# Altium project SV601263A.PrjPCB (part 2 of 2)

## Sheet SV601263A_Power.SchDoc
size 431 x 279 mm; Date: Not shown in title block; ApprovedBy: Not shown in title block; CheckedBy: Not shown in title block; Author: Not shown in title block; CompanyName: Not shown in title block; Engineer: Not shown in title block; Organization: Not shown in title block; Address1: Not shown in title block; Address2: Not shown in title block; Address3: Not shown in title block; Address4: Not shown in title block; DocumentNumber: 9; Revision: Use project parameter SCH_Rev; SheetNumber: 6; SheetTotal: 8; PageSetup: Record=PageOptions¦CenterHorizontal=True¦CenterVertical=True¦PrintScale=0.96¦XCorrection=1.00¦YCorrection=1.00¦PrintKind=0¦BorderSize=5000000¦LeftOffset=0¦BottomOffset=0¦Orientation=2¦PaperLength=1000¦PaperWidth=1000¦Scale=100¦PaperSource=15¦PrintQuality=600¦MediaType=1¦DitherType=10¦PaperKind=11x17¦PrintScaleMode=1
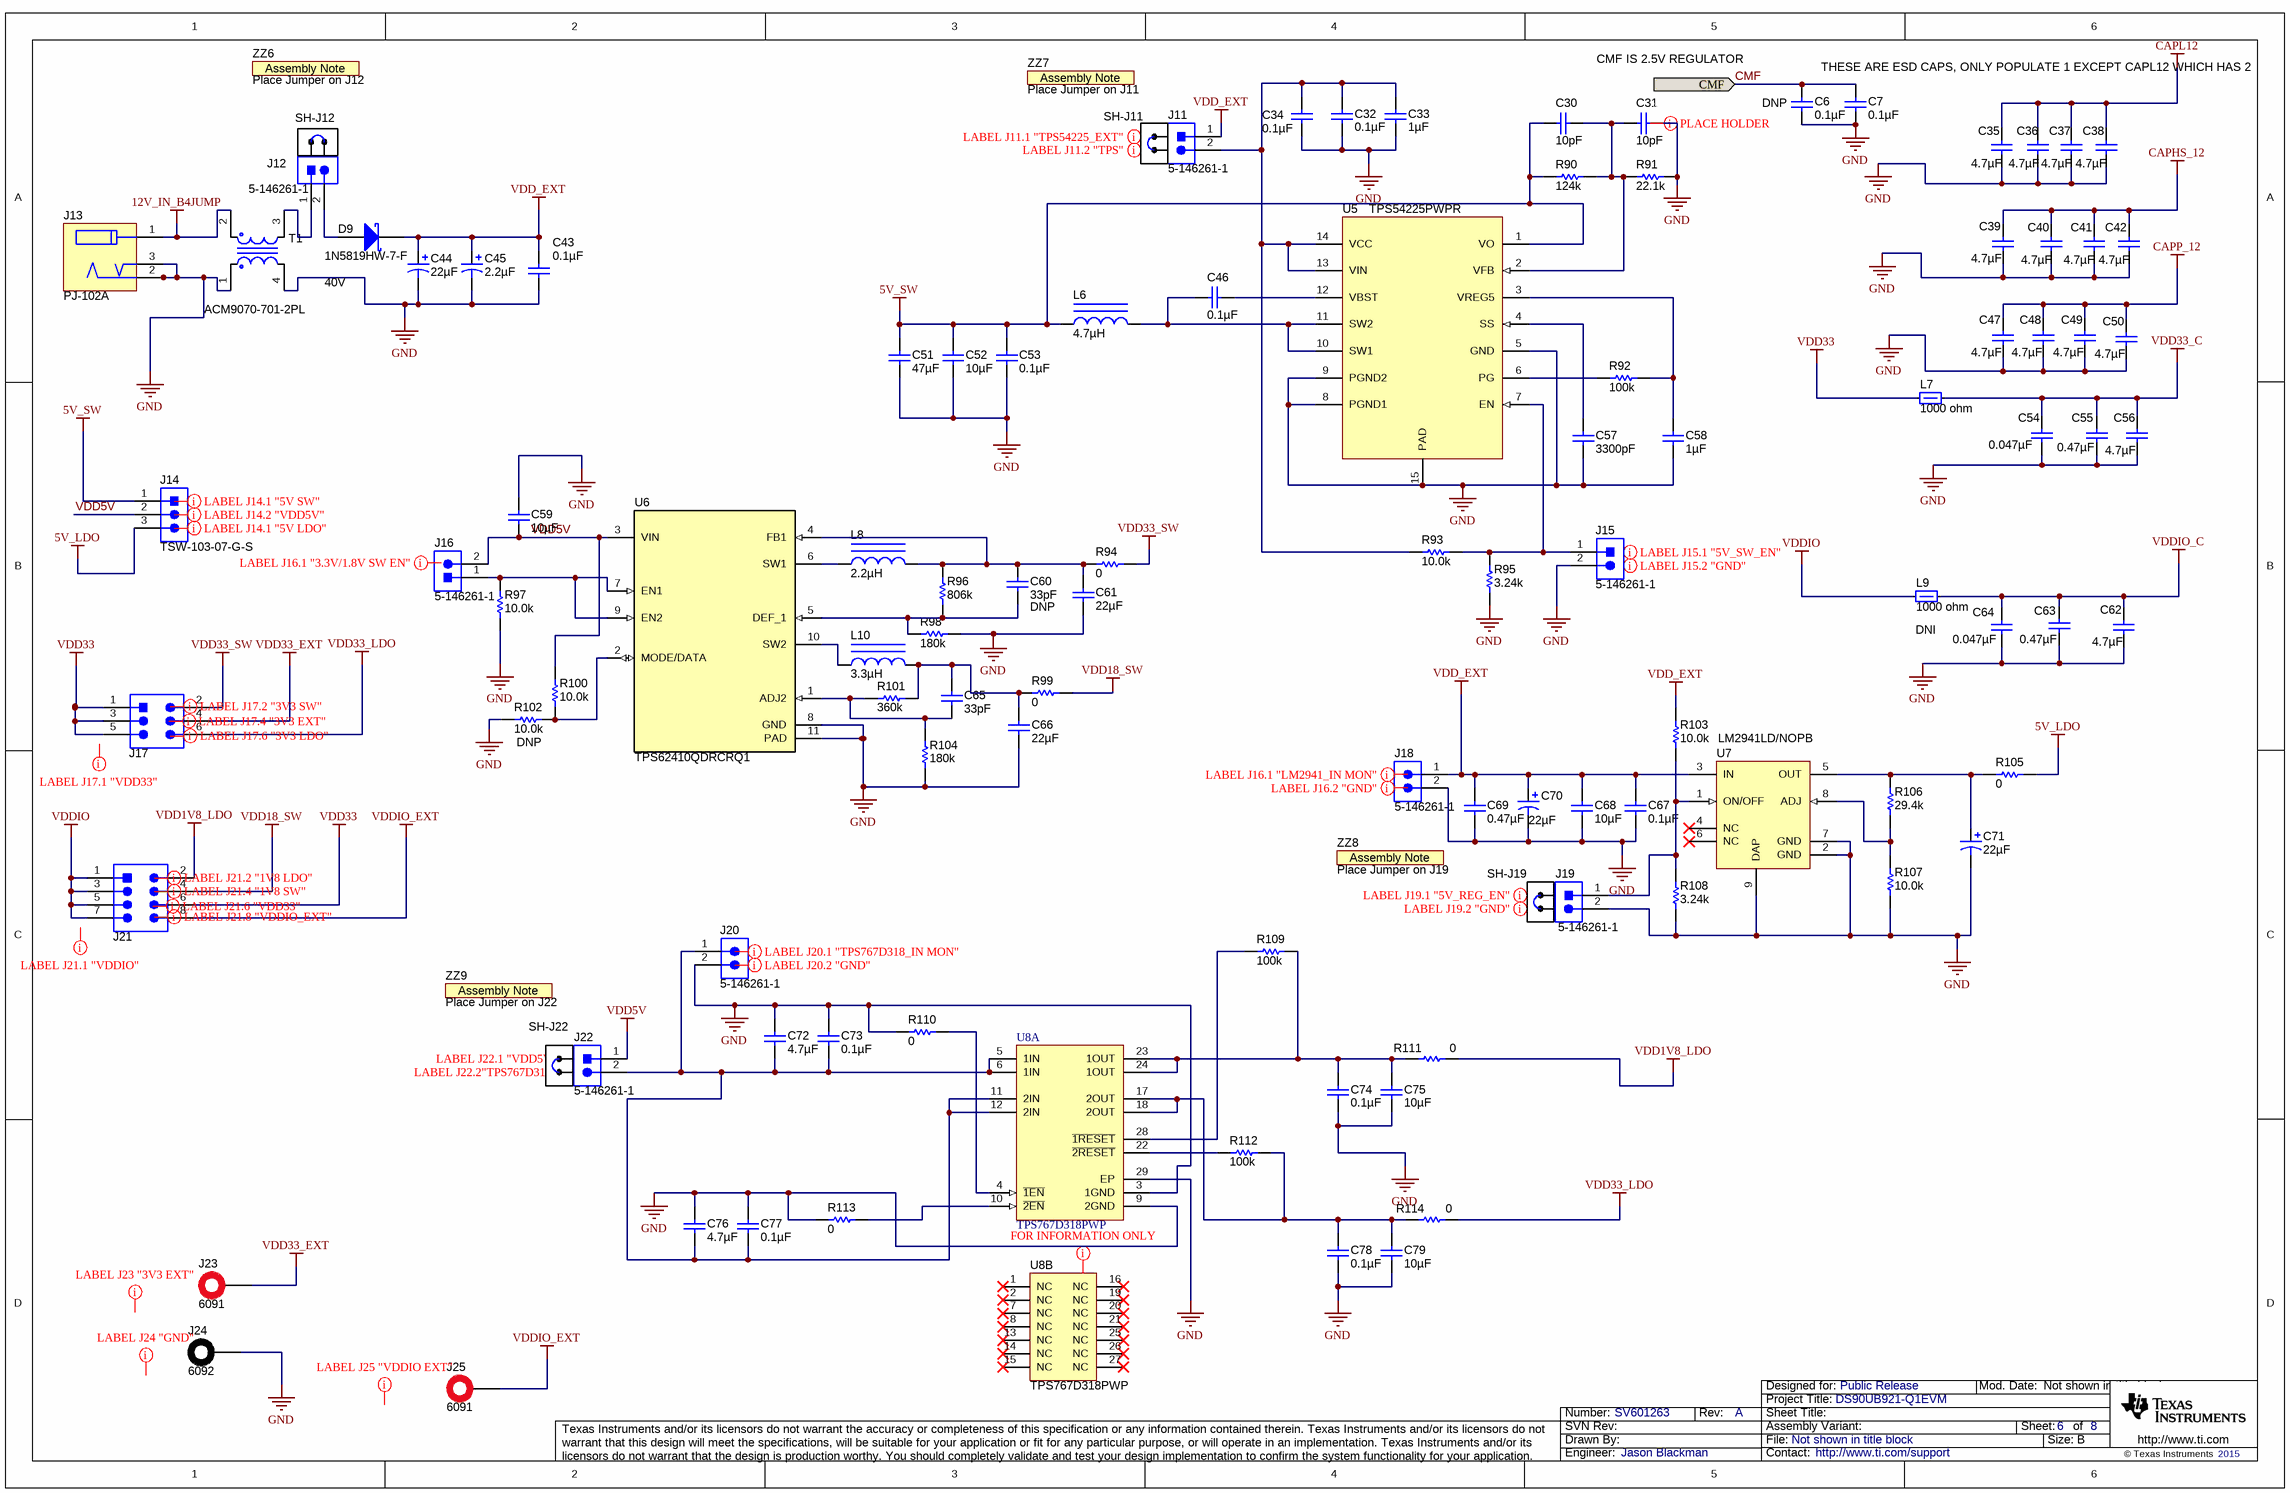
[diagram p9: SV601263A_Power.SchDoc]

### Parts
C6  DNP  ValueDisplayed: 0.1µF  [0603]
C7  ValueDisplayed: 0.1µF  [0603]  (hidden comment: GRM188R61C104KA01D)
C30  ValueDisplayed: 10pF  [0402]  (hidden comment: GRM1555C1H100JA01D)
C31  ValueDisplayed: 10pF  [0402]  (hidden comment: GRM1555C1H100JA01D)
C32  ValueDisplayed: 0.1µF  [0402]  (hidden comment: GRM155R71C104KA88D)
C33  ValueDisplayed: 1µF  [0603]  (hidden comment: C1608X7R1C105K080AC)
C34  ValueDisplayed: 0.1µF  [0402]  (hidden comment: GRM155R71C104KA88D)
C35  ValueDisplayed: 4.7µF  [0805_HV]  (hidden comment: GCM21BR71C475KA73L)
C36  ValueDisplayed: 4.7µF  [0805_HV]  (hidden comment: GCM21BR71C475KA73L)
C37  ValueDisplayed: 4.7µF  [0805_HV]  (hidden comment: GCM21BR71C475KA73L)
C38  ValueDisplayed: 4.7µF  [0805_HV]  (hidden comment: GCM21BR71C475KA73L)
C39  ValueDisplayed: 4.7µF  [0805_HV]  (hidden comment: GCM21BR71C475KA73L)
C40  ValueDisplayed: 4.7µF  [0805_HV]  (hidden comment: GCM21BR71C475KA73L)
C41  ValueDisplayed: 4.7µF  [0805_HV]  (hidden comment: GCM21BR71C475KA73L)
C42  ValueDisplayed: 4.7µF  [0805_HV]  (hidden comment: GCM21BR71C475KA73L)
C43  ValueDisplayed: 0.1µF  [0402]  (hidden comment: GRM155R71C104KA88D)
C44  ValueDisplayed: 22µF  [7343-31]  (hidden comment: 293D226X0025D2TE3)
C45  ValueDisplayed: 2.2µF  [3216-18]  (hidden comment: 293D225X9025A2TE3)
C46  ValueDisplayed: 0.1µF  [0402]  (hidden comment: GRM155R71C104KA88D)
C47  ValueDisplayed: 4.7µF  [0805_HV]  (hidden comment: GCM21BR71C475KA73L)
C48  ValueDisplayed: 4.7µF  [0805_HV]  (hidden comment: GCM21BR71C475KA73L)
C49  ValueDisplayed: 4.7µF  [0805_HV]  (hidden comment: GCM21BR71C475KA73L)
C50  ValueDisplayed: 4.7µF  [0805_HV]  (hidden comment: GCM21BR71C475KA73L)
C51  ValueDisplayed: 47µF  [1210]  (hidden comment: GRM32ER61C476ME15L)
C52  ValueDisplayed: 10µF  [0805_HV]  (hidden comment: GRM21BR71A106KE51L)
C53  ValueDisplayed: 0.1µF  [0402]  (hidden comment: GRM155R71C104KA88D)
C54  ValueDisplayed: 0.047µF  [0402]  (hidden comment: GRM155R71C473KA01D)
C55  ValueDisplayed: 0.47µF  [0603]  (hidden comment: GRM188R71E474KA12D)
C56  ValueDisplayed: 4.7µF  [0805_HV]  (hidden comment: GCM21BR71C475KA73L)
C57  ValueDisplayed: 3300pF  [0402]  (hidden comment: GRM155R71H332KA01D)
C58  ValueDisplayed: 1µF  [0603]  (hidden comment: C1608X7R1C105K080AC)
C59  ValueDisplayed: 10µF  [0603]  (hidden comment: GRM188R61E106MA73D)
C60  DNP  ValueDisplayed: 33pF  [0603]
C61  ValueDisplayed: 22µF  [1206_190]  (hidden comment: C3216X5R1V226M160AC)
C62  ValueDisplayed: 4.7µF  [0805_HV]  (hidden comment: GCM21BR71C475KA73L)
C63  ValueDisplayed: 0.47µF  [0603]  (hidden comment: GRM188R71E474KA12D)
C64  ValueDisplayed: 0.047µF  [0402]  (hidden comment: GRM155R71C473KA01D)
C65  ValueDisplayed: 33pF  [0603]  (hidden comment: 06035A330JAT2A)
C66  ValueDisplayed: 22µF  [1206_190]  (hidden comment: C3216X5R1V226M160AC)
C67  ValueDisplayed: 0.1µF  [0402]  (hidden comment: C1005X7R1H104K050BB)
C68  ValueDisplayed: 10µF  [0603]  (hidden comment: GRM188R61E106MA73D)
C69  ValueDisplayed: 0.47µF  [0402]  (hidden comment: GRM155R61C474KE01)
C70  ValueDisplayed: 22µF  [7343-31]  (hidden comment: 293D226X0025D2TE3)
C71  ValueDisplayed: 22µF  [7343-31]  (hidden comment: 293D226X0025D2TE3)
C72  ValueDisplayed: 4.7µF  [0805_HV]  (hidden comment: GRM21BR71C475KA73L)
C73  ValueDisplayed: 0.1µF  [0402]  (hidden comment: GRM155R71C104KA88D)
C74  ValueDisplayed: 0.1µF  [0402]  (hidden comment: GRM155R71C104KA88D)
C75  ValueDisplayed: 10µF  [0805_HV]  (hidden comment: GRM21BR71A106KE51L)
C76  ValueDisplayed: 4.7µF  [0805_HV]  (hidden comment: GRM21BR71C475KA73L)
C77  ValueDisplayed: 0.1µF  [0402]  (hidden comment: GRM155R71C104KA88D)
C78  ValueDisplayed: 0.1µF  [0402]  (hidden comment: GRM155R71C104KA88D)
C79  ValueDisplayed: 10µF  [0805_HV]  (hidden comment: GRM21BR71A106KE51L)
D9  1N5819HW-7-F  value 40V  [SOD-123]
J11  5-146261-1  [CONN_5-146261-1]
J12  5-146261-1  [CONN_5-146261-1]
J13  PJ-102A  [CONN_PJ-102A]
J14  TSW-103-07-G-S  [TSW-103-07-G-S]
J15  5-146261-1  [CONN_5-146261-1]
J16  5-146261-1  [CONN_5-146261-1]
J17  TSW-103-07-G-D  [TSW-103-07-G-D]  (value not drawn)
J18  5-146261-1  [CONN_5-146261-1]
J19  5-146261-1  [CONN_5-146261-1]
J20  5-146261-1  [CONN_5-146261-1]
J21  TSW-104-07-G-D  [TSW-104-07-G-D]  (value not drawn)
J22  5-146261-1  [CONN_5-146261-1]
J23  6091  [6091]
J24  6092  [6092]
J25  6091  [6091]
L6  ValueDisplayed: 4.7µH  [WE-TPC-XLH2]  (hidden comment: 7440650047)
L7  value 1000 ohm  [0402]  (hidden comment: BLM15AX102SN1D)
L8  ValueDisplayed: 2.2µH  [VLF302510MT]  (hidden comment: VLF302510MT-2R2M)
L9  value 1000 ohm  [0402]  (hidden comment: BLM15AX102SN1D)
L10  ValueDisplayed: 3.3µH  [MLP2520S-S]  (hidden comment: MLP2520S3R3ST0S1)
R90  value 124k  [0402]  (hidden comment: CRCW0402124KFKED)
R91  value 22.1k  [0402]  (hidden comment: CRCW040222K1FKED)
R92  value 100k  [0402]  (hidden comment: CRCW0402100KJNED)
R93  ValueDisplayed: 10.0k  [0402]  (hidden comment: CRCW040210K0FKED)
R94  value 0  [0402]  (hidden comment: ERJ-2GE0R00X)
R95  value 3.24k  [0402]  (hidden comment: CRCW04023K24FKED)
R96  ValueDisplayed: 806k  [0805_HV]  (hidden comment: RT0805BRD07806KL)
R97  ValueDisplayed: 10.0k  [0402]  (hidden comment: CRCW040210K0FKED)
R98  ValueDisplayed: 180k  [0603]  (hidden comment: RG1608P-184-B-T5)
R99  value 0  [0402]  (hidden comment: ERJ-2GE0R00X)
R100  ValueDisplayed: 10.0k  [0402]  (hidden comment: CRCW040210K0FKED)
R101  ValueDisplayed: 360k  [0603]  (hidden comment: ERJ-3EKF3603V)
R102  DNP  ValueDisplayed: 10.0k  [0402]
R103  ValueDisplayed: 10.0k  [0402]  (hidden comment: CRCW040210K0FKED)
R104  ValueDisplayed: 180k  [0603]  (hidden comment: RG1608P-184-B-T5)
R105  value 0  [0402]  (hidden comment: ERJ-2GE0R00X)
R106  ValueDisplayed: 29.4k  [0402]  (hidden comment: CRCW040229K4FKED)
R107  ValueDisplayed: 10.0k  [0402]  (hidden comment: CRCW040210K0FKED)
R108  value 3.24k  [0402]  (hidden comment: CRCW04023K24FKED)
R109  value 100k  [0402]  (hidden comment: CRCW0402100KJNED)
R110  value 0  [0402]  (hidden comment: ERJ-2GE0R00X)
R111  ValueDisplayed: 0  [0603]  (hidden comment: CRCW06030000Z0EA)
R112  value 100k  [0402]  (hidden comment: CRCW0402100KJNED)
R113  value 0  [0402]  (hidden comment: ERJ-2GE0R00X)
R114  ValueDisplayed: 0  [0603]  (hidden comment: CRCW06030000Z0EA)
SH-J11  969102-0000-DA  [SNT-100-BK-G]  (value not drawn)
SH-J12  969102-0000-DA  [SNT-100-BK-G]  (value not drawn)
SH-J19  969102-0000-DA  [SNT-100-BK-G]  (value not drawn)
SH-J22  969102-0000-DA  [SNT-100-BK-G]  (value not drawn)
T1  ACM9070-701-2PL  [ACM9070]
U5  TPS54225PWPR  [PWP0014E_N]
U6  TPS62410QDRCRQ1  [DRC0010J]
U7  LM2941LD/NOPB  [LDC08A]
U8  TPS767D318PWP  [PWP0028D_N]  (parts A,B of 2)
ZZ6  Place Jumper on J12  [AssemblyNote]  (no BOM)
ZZ7  Place Jumper on J11  [AssemblyNote]  (no BOM)
ZZ8  Place Jumper on J19  [AssemblyNote]  (no BOM)
ZZ9  Place Jumper on J22  [AssemblyNote]  (no BOM)

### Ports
CMF

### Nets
5V_LDO: J14.3 R105.2
5V_SW: C30.2 C51.1 C52.1 C53.2 J14.1 L6.1 R90.1 U5.1(VO)
12V_IN_B4JUMP: J13.1 T1.2
CAPHS_12: C39.1 C40.1 C41.1 C42.1
CAPL12: C35.1 C36.1 C37.1 C38.1
CAPP_12: C47.1 C48.1 C49.1 C50.1
GND: C6.2 C7.2 C31.1 C32.2 C33.2 C34.2 C35.2 C36.2 C37.2 C38.2 C39.2 C40.2 C41.2 C42.2 C43.1 C44.2(-) C45.2(-) C47.2 C48.2 C49.2 C50.2 C51.2 C52.2 C53.1 C54.2 C55.2 C56.2 C57.2 C58.2 C59.1 C61.2 C62.2 C63.2 C64.2 C66.2 C67.2 C68.2 C69.2 C70.2(-) C71.2(-) C72.1 C73.2 C74.1 C75.2 C76.1 C77.2 C78.1 C79.2 J13.2 J13.3 J15.2 J18.2 J19.2 J20.2 J24.1 R91.2 R95.1 R97.1 R98.1 R102.1 R104.1 R107.1 R108.1 R110.1 R113.1 T1.1 T1.4 U5.5(GND) U5.8(PGND1) U5.9(PGND2) U5.15(PAD) U6.8(GND) U6.11(PAD) U7.2(GND) U7.7(GND) U7.9(DAP) U8.3(1GND) U8.9(2GND) U8.29(EP)
VDD1V8_LDO: J21.2 R111.2
VDD5V: C59.2 J14.2 J16.2 J22.1 R100.2 U6.3(VIN)
VDD18_SW: J21.4 R99.2
VDD33: J17.1 J17.3 J17.5 J21.6 L7.1
VDD33_C: C54.1 C55.1 C56.1 L7.2
VDD33_EXT: J17.4 J23.1
VDD33_LDO: J17.6 R114.2
VDD33_SW: J17.2 R94.2
VDD_EXT: C43.2 C44.1(+) C45.1(+) C67.1 C68.1 C69.1 C70.1(+) D9.1(K) J11.1 J18.1 R103.2 U7.3(IN)
VDDIO: J21.1 J21.3 J21.5 J21.7 L9.1
VDDIO_C: C62.1 C63.1 C64.1 L9.2
VDDIO_EXT: J21.8 J25.1
CMF: C6.1 C7.1 ; port CMF
NetC30_1: C30.1 C31.2 R90.2 R91.1 U5.2(VFB)
NetC32_1: C32.1 C33.1 C34.1 J11.2 R93.1 U5.13(VIN) U5.14(VCC)
NetC46_1: C46.1 U5.12(VBST)
NetC46_2: C46.2 L6.2 U5.10(SW1) U5.11(SW2)
NetC57_1: C57.1 U5.4(SS)
NetC58_1: C58.1 R92.2 U5.3(VREG5)
NetC60_1: C60.1 C61.1 L8.2 R94.1 R96.1 U6.4(FB1)
NetC60_2: C60.2 R96.2 R98.2 U6.5(DEF_1)
NetC65_1: C65.1 C66.1 L10.2 R99.1 R101.2
NetC65_2: C65.2 R101.1 R104.2 U6.1(ADJ2)
NetC71_1: C71.1(+) R105.1 R106.2 U7.5(OUT)
NetC72_2: C72.2 C73.1 C76.2 C77.1 J20.1 J22.2 U8.5(1IN) U8.6(1IN) U8.11(2IN) U8.12(2IN)
NetC74_2: C74.2 C75.1 R109.1 R111.1 U8.23(1OUT) U8.24(1OUT)
NetC78_2: C78.2 C79.1 R112.2 R114.1 U8.17(2OUT) U8.18(2OUT)
NetD9_2: D9.2(A) J12.2
NetJ12_1: J12.1 T1.3
NetJ15_1: J15.1 R93.2 R95.2 U5.7(EN)
NetJ16_1: J16.1 R97.2 U6.7(EN1) U6.9(EN2)
NetJ19_1: J19.1 R103.1 R108.2 U7.1(ON/OFF)
NetL8_1: L8.1 U6.6(SW1)
NetL10_1: L10.1 U6.10(SW2)
NetR92_1: R92.1 U5.6(PG)
NetR100_1: R100.1 R102.2 U6.2(MODE/DATA)
NetR106_1: R106.1 R107.2 U7.8(ADJ)
NetR109_2: R109.2 U8.28(~{1RESET})
NetR110_2: R110.2 U8.4(~{1EN})
NetR112_1: R112.1 U8.22(~{2RESET})
NetR113_2: R113.2 U8.10(~{2EN})

Not connected (* = marked no-connect by the designer): U7 4(NC)* 6(NC)*; U8 1(NC)* 2(NC)* 7(NC)* 8(NC)* 13(NC)* 14(NC)* 15(NC)* 16(NC)* 19(NC)* 20(NC)* 21(NC)* 25(NC)* 26(NC)* 27(NC)*

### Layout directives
rule Undefined: (no net found under the mark)

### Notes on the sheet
- CMF IS 2.5V REGULATOR
- (near C7) THESE ARE ESD CAPS, ONLY POPULATE 1 EXCEPT CAPL12 WHICH HAS 2
- (near L9) DNI

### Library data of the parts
C6 C7 = GRM188R61C104KA01D: CAP, CERM, 0.1 µF, 16 V, +/- 10%, X5R, 0603; Manufacturer: MuRata; Polarized: N; CompType: Capacitor; Value: 0.1uF; U/M: EA; Cap_F: 0.0000001; Tolerance_%: 10; Value1: Unknown; VDC_V: 16; Value2: 16V; TaMin_C: -55; TaMax_C: 85; AEC Category: Q200
C30 C31 = GRM1555C1H100JA01D: CAP, CERM, 10pF, 50V, +/-5%, C0G/NP0, 0402; Manufacturer: MuRata; Polarized: N; CompType: Capacitor; U/M: EA; Cap_F: 0.00000000001; Tolerance_%: 5; Value1: Unknown; VDC_V: 50; TaMin_C: -55; TaMax_C: 125
C32 C34 C43 C46 C53 C73 C74 C77 C78 = GRM155R71C104KA88D: CAP, CERM, 0.1uF, 16V, +/-10%, X7R, 0402; Manufacturer: MuRata; Polarized: N; CompType: Capacitor; U/M: EA; Cap_F: 0.0000001; Tolerance_%: 10; Value1: Unknown; VDC_V: 16; TaMin_C: -55; TaMax_C: 125
C33 C58 = C1608X7R1C105K080AC: CAP, CERM, 1 µF, 16 V, +/- 10%, X7R, 0603; Manufacturer: TDK; Polarized: N; CompType: Capacitor; Value: 1uF; U/M: EA; Cap_F: 0.000001; Tolerance_%: 10; ESR_ohm: 0.0057; Value1: 0.0057 ohm; VDC_V: 16; Value2: 16V; TaMin_C: -55; TaMax_C: 125; AEC Category: Q200
C35-C42 C47-C50 C56 C62 = GCM21BR71C475KA73L: CAP, CERM, 4.7 µF, 16 V, +/- 10%, X7R, AEC-Q200 Grade 1, 0805; Manufacturer: MuRata; Polarized: N; CompType: Capacitor; Value: 4.7uF; U/M: EA; Cap_F: 0.0000047; Tolerance_%: 10; Value1: Unknown; VDC_V: 16; Value2: 16V; TaMin_C: -55; TaMax_C: 125; Cap_Case: 0805; AEC Category: Q200; AEC Qualified: Y; AEC Grade: 1
C44 C70 C71 = 293D226X0025D2TE3: CAP, TA, 22uF, 25V, +/-20%, 0.7 ohm, SMD; Manufacturer: Vishay-Sprague; Polarized: Y; CompType: Capacitor; U/M: EA; Cap_F: 0.000022; Tolerance_%: 20; Value1: 0.7 ohm; VDC_V: 25; ESR_Ohm: 0.7; IRMS_A: 0.46; TaMin_C: -55; TaMax_C: 125; Cap_Case: D
C45 = 293D225X9025A2TE3: CAP, TA, 2.2uF, 25V, +/-10%, 6.3 ohm, SMD; Manufacturer: Vishay-Sprague; Polarized: Y; CompType: Capacitor; U/M: EA; Cap_F: 0.0000022; Tolerance_%: 10; Value1: 6.3 ohm; VDC_V: 25; ESR_Ohm: 6.3; IRMS_A: 0.11; TaMin_C: -55; TaMax_C: 125; Cap_Case: A
C51 = GRM32ER61C476ME15L: CAP, CERM, 47uF, 16V, +/-20%, X5R, 1210; Manufacturer: MuRata; Polarized: N; CompType: Capacitor; U/M: EA; Cap_F: 0.000047; Tolerance_%: 20; ESR_Ohm: 0.002; Value1: 0.002 ohm; VDC_V: 16; TaMin_C: -55; TaMax_C: 85
C52 C75 C79 = GRM21BR71A106KE51L: CAP, CERM, 10uF, 10V, +/-10%, X7R, 0805; Manufacturer: MuRata; Polarized: N; CompType: Capacitor; U/M: EA; Cap_F: 0.00001; Tolerance_%: 10; ESR_Ohm: 0.003; Value1: 0.003 ohm; TaMin_C: -55; TaMax_C: 125; Cap_Case: 0805
C54 C64 = GRM155R71C473KA01D: CAP, CERM, 0.047 µF, 16 V, +/- 10%, X7R, 0402; Manufacturer: MuRata; Polarized: N; CompType: Capacitor; Value: 0.047uF; U/M: EA; Cap_F: 0.000000047; Tolerance_%: 10; Value1: Unknown; VDC_V: 16; Value2: 16V; TaMin_C: -55; TaMax_C: 125; AEC Category: Q200
C55 C63 = GRM188R71E474KA12D: CAP, CERM, 0.47 µF, 25 V, +/- 10%, X7R, 0603; Manufacturer: MuRata; Polarized: N; CompType: Capacitor; Value: 0.47uF; U/M: EA; Cap_F: 0.00000047; Tolerance_%: 10; Value1: Unknown; VDC_V: 25; Value2: 25V; TaMin_C: -55; TaMax_C: 125; AEC Category: Q200
C57 = GRM155R71H332KA01D: CAP, CERM, 3300pF, 50V, +/-10%, X7R, 0402; Manufacturer: MuRata; Polarized: N; CompType: Capacitor; U/M: EA; Cap_F: 0.0000000033; Tolerance_%: 10; Value1: Unknown; VDC_V: 50; TaMin_C: -55; TaMax_C: 125
C59 C68 = GRM188R61E106MA73D: CAP, CERM, 10 µF, 25 V, +/- 20%, X5R, 0603; Manufacturer: MuRata; Polarized: N; CompType: Capacitor; Value: 10uF; U/M: EA; Cap_F: 0.00001; Tolerance_%: 20; Value1: Unknown; VDC_V: 25; Value2: 25V; TaMin_C: -55; TaMax_C: 85; AEC Category: Q200
C60 C65 = 06035A330JAT2A: CAP, CERM, 33 pF, 50 V, +/- 5%, C0G/NP0, 0603; Manufacturer: AVX; Polarized: N; CompType: Capacitor; Value: 33pF; U/M: EA; Cap_F: 0.000000000033; Tolerance_%: 5; ESR_ohm: 0.209; Value1: 0.209 ohm; VDC_V: 50; Value2: 50V; TaMin_C: -55; TaMax_C: 125; AEC Category: Q200
C61 C66 = C3216X5R1V226M160AC: CAP, CERM, 22 µF, 35 V, +/- 20%, X5R, 1206_190; Manufacturer: TDK; Polarized: N; CompType: Capacitor; Value: 22uF; U/M: EA; Cap_F: 0.000022; Tolerance_%: 20; ESR_ohm: 0.002246; Value1: 0.002246 ohm; VDC_V: 35; Value2: 35V; TaMin_C: -55; TaMax_C: 85; Cap_Case: 1206; AEC Category: Q200
C67 = C1005X7R1H104K050BB: CAP, CERM, 0.1 µF, 50 V, +/- 10%, X7R, 0402; Manufacturer: TDK; Polarized: N; CompType: Capacitor; Value: 0.1uF; U/M: EA; Cap_F: 0.0000001; Tolerance_%: 10; Value1: Unknown; VDC_V: 50; Value2: 50V; TaMin_C: -55; TaMax_C: 125; AEC Category: Q200
C69 = GRM155R61C474KE01: CAP, CERM, 0.47 µF, 16 V, +/- 10%, X5R, 0402; Manufacturer: MuRata; Polarized: N; CompType: Capacitor; Value: 0.47uF; U/M: EA; Cap_F: 0.00000047; Tolerance_%: 10; Value1: Unknown; VDC_V: 16; Value2: 16V; TaMin_C: -55; TaMax_C: 85; AEC Category: Q200
C72 C76 = GRM21BR71C475KA73L: CAP, CERM, 4.7uF, 16V, +/-10%, X7R, 0805; Manufacturer: MuRata; Polarized: N; CompType: Capacitor; U/M: EA; Cap_F: 0.0000047; Tolerance_%: 10; ESR_Ohm: 0.006; Value1: 0.006 ohm; VDC_V: 16; TaMin_C: -55; TaMax_C: 125; Cap_Case: 0805
D9 = 1N5819HW-7-F: Diode, Schottky, 40V, 1A, SOD-123; Manufacturer: Diodes Inc.; U/M: EA; Vf_V: 0.45; Value2: 0.45V; Io_A: 1; Vr_V: 40; TJmax_C: 125
J11 J12 J15 J16 J18-J20 J22 = 5-146261-1: Header, 100mil, 2x1, Gold, TH; Manufacturer: TE Connectivity; SymbolCreator: a0412235; U/M: EA
J13 = PJ-102A: Connector, DC Jack 2.1X5.5 mm, TH; Manufacturer: CUI Inc.; SymbolCreator: a0799628; U/M: EA
J14 = TSW-103-07-G-S: Header, 100mil, 3x1, Gold, TH; Manufacturer: Samtec; SymbolCreator: a0799628; U/M: EA
J17 = TSW-103-07-G-D: Header, 100mil, 3x2, Gold, TH; Manufacturer: Samtec; SymbolCreator: a0412235; Pitch_mm: 2.54; Gender: Male; Shrouded: N; Row_Count: 2; Current_A: 6.3; Voltage_V: 550; Cert_CSA: Y
J21 = TSW-104-07-G-D: Header, 100mil, 4x2, Gold, TH; Manufacturer: Samtec; SymbolCreator: a0411947; Pitch_mm: 2.54; Gender: Male; Shrouded: N; Row_Count: 2; Current_A: 6.3; Voltage_V: 550; Cert_CSA: Y
J23 J25 = 6091: Standard Banana Jack, Insulated, Red; Manufacturer: Keystone; SymbolCreator: a0412235; CompType: Connector; U/M: EA
J24 = 6092: Standard Banana Jack, Insulated, Black; Manufacturer: Keystone; SymbolCreator: a0412235; CompType: Connector; U/M: EA
L6 = 7440650047: Inductor, Shielded Drum Core, Ferrite, 4.7 µH, 4.2 A, 0.02 ohm, SMD; Manufacturer: Wurth Elektronik; Value: 4.7uH; Ind_H: 4.7E-6; Imax_A: 4.2; Irms: 4.6A @ 30C rise; Isat: 4.2A @ 35% inductance drop; DCR_ohm: 0.02; Value2: 4.2A; AEC Category: Q200
L7 L9 = BLM15AX102SN1D: Ferrite Bead, 1000 ohm @ 100 MHz, 0.35 A, 0402; Manufacturer: MuRata; Imax_A: 0.35; DCR_ohm: 0.49; Value1: 0.49 ohm; Value2: 0.35A; ZTyp@100MHz_Ohm: 1000
L8 = VLF302510MT-2R2M: Inductor, Shielded, Ferrite, 2.2 µH, 1.23 A, 0.084 ohm, SMD; Manufacturer: TDK; Value: 2.2uH; Ind_H: 2.2E-6; Imax_A: 1.23; Irms: 1.5A @ 40C rise; Isat: 1.23A @ 30% inductance drop; DCR_ohm: 0.084; Value2: 1.23A; AEC Category: Q200
L10 = MLP2520S3R3ST0S1: Inductor, Multilayer, Ferrite, 3.3 µH, 0.6 A, 0.143 ohm, SMD; Manufacturer: TDK; Value: 3.3uH; Ind_H: 3.3E-6; Imax_A: 0.6; Irms: 1.4A @ 40C rise; Isat: 0.6A @ 30% inductance drop; DCR_ohm: 0.143; Value2: 0.6A; AEC Category: Q200
R90 = CRCW0402124KFKED: RES, 124k ohm, 1%, 0.063W, 0402; Manufacturer: Vishay-Dale; CompType: Resistor; Res_ohm: 124000; Tolerance_%: 1; Power_W: 0.063; VDC_V: 50; TempCo: 100 ppm/C; EIA_Code: E96; U/M: EA
R91 = CRCW040222K1FKED: RES, 22.1k ohm, 1%, 0.063W, 0402; Manufacturer: Vishay-Dale; CompType: Resistor; Res_ohm: 22100; Value_Code: 22k1; Tolerance_%: 1; Power_W: 0.063; VDC_V: 50; TempCo: 100 ppm/C; EIA_Code: E96; U/M: EA
R92 R109 R112 = CRCW0402100KJNED: RES, 100k ohm, 5%, 0.063W, 0402; Manufacturer: Vishay-Dale; CompType: Resistor; Res_ohm: 100000; Tolerance_%: 5; Power_W: 0.063; VDC_V: 50; TempCo: 200 ppm/C; EIA_Code: E24; U/M: EA
R93 R97 R100 R102 R103 R107 = CRCW040210K0FKED: RES, 10.0 k, 1%, 0.063 W, 0402; Manufacturer: Vishay-Dale; CompType: Resistor; Value: 10.0k; Res_ohm: 10000; Value_Code: 10k0; Tolerance_%: 1; Power_W: 0.063; Value2: 0.063W; VDC_V: 50; TempCo: 100 ppm/C; EIA_Code: E96; U/M: EA
R94 R99 R105 R110 R113 = ERJ-2GE0R00X: RES, 0 ohm, 5%, 0.063W, 0402; Manufacturer: Panasonic; CompType: Resistor; Value_Code: 0000; Tolerance_%: 5; Power_W: 0.063; VDC_V: 50; TempCo: 600 ppm/C; EIA_Code: E24; U/M: EA
R95 R108 = CRCW04023K24FKED: RES, 3.24k ohm, 1%, 0.063W, 0402; Manufacturer: Vishay-Dale; CompType: Resistor; Res_ohm: 3240; Value_Code: 3k24; Tolerance_%: 1; Power_W: 0.063; VDC_V: 50; TempCo: 100 ppm/C; EIA_Code: E96; U/M: EA
R96 = RT0805BRD07806KL: RES, 806 k, 0.1%, 0.125 W, 0805; Manufacturer: Yageo America; CompType: Resistor; Value: 806k; Res_ohm: 806000; Tolerance_%: 0.1; Power_W: 0.125; Value2: 0.125W; VDC_V: 150; TempCo: 25 ppm/C; EIA_Code: E192; U/M: EA; AEC Category: Q200
R98 R104 = RG1608P-184-B-T5: RES, 180 k, 0.1%, 0.1 W, 0603; Manufacturer: Susumu Co Ltd; CompType: Resistor; Value: 180k; Res_ohm: 180000; Tolerance_%: 0.1; Value2: 0.1W; VDC_V: 75; TempCo: 25 ppm/C; EIA_Code: E192; U/M: EA; AEC Category: Q200
R101 = ERJ-3EKF3603V: RES, 360 k, 1%, 0.1 W, AEC-Q200 Grade 0, 0603; Manufacturer: Panasonic; CompType: Resistor; Value: 360k; Res_ohm: 360000; Tolerance_%: 1; Power_W: 0.1; Value2: 0.1W; VDC_V: 75; TempCo: 100 ppm/C; U/M: EA; AEC Category: Q200; AEC Qualified: Y; AEC Grade: 0
R106 = CRCW040229K4FKED: RES, 29.4 k, 1%, 0.063 W, 0402; Manufacturer: Vishay-Dale; CompType: Resistor; Value: 29.4k; Res_ohm: 29400; Value_Code: 29k4; Tolerance_%: 1; Power_W: 0.063; Value2: 0.063W; VDC_V: 50; TempCo: 100 ppm/C; EIA_Code: E96; U/M: EA
R111 R114 = CRCW06030000Z0EA: RES, 0, 5%, 0.1 W, 0603; Manufacturer: Vishay-Dale; CompType: Resistor; Value: 0; Value_Code: 0000; Tolerance_%: 5; Power_W: 0.1; Value2: 0.1W; VDC_V: 75; TempCo: 200 ppm/C; EIA_Code: E24; U/M: EA
SH-J11 SH-J12 SH-J19 SH-J22 = 969102-0000-DA: Shunt, 100mil, Gold plated, Black; Manufacturer: 3M; Alternate Manufacturer: Samtec; Value: 1x2; Note: You can "mate" this to a header by matching the designator.  i.e. use SH-J3 for header J3
T1 = ACM9070-701-2PL: Common Mode Filter for Power Line; Manufacturer: TDK; Alternate Manufacturer: None; CompType: SMD; DCR_Ohm: 0.010; VDC_V: 50; ZTyp@100MHz_Ohm: 700; U/M: EA
U5 = TPS54225PWPR: 4.5V to 18V Input, 2-A Synchronous Step-Down SWIFT™ Converter, PWP0014E; Manufacturer: Texas Instruments; SymbolCreator: Altium; CompType: IC; U/M: EA
U6 = TPS62410QDRCRQ1: 2.25MHz 2x800mA Dual Step Down Converter In Small 3x3mm QFN Package, DRC0010J; Manufacturer: Texas Instruments; SymbolCreator: a0411947; CompType: IC; U/M: EA
U7 = LM2941LD/NOPB: 1A Low Dropout Adjustable Regulator, 8-pin LLP, Pb-Free; Manufacturer: Texas Instruments; PackageTopMarking: NS*UZXYTT*L2941LD; PowerWise: N; CompType: LDO IC
U8 = TPS767D318PWP: Dual Output LDO, 1 A, Fixed 1.8, 3.3 V Output, 2.7 to 10 V Input, 28-pin HTSSOP (PWP), -40 to 125 degC, Green (RoHS & no Sb/Br); Manufacturer: Texas Instruments; Alternate Manufacturer: None; Alternate PartNumber: Equivalent; Iout(Max)(A): 1; Iq(Typ)(mA): 0.08; SubFamily: Dual Channel LDO; Vdo(Typ)(mV): 350; Vin(Max)(V): 10; Vin(Min)(V): 2.7; Vout(Max)(V): 3.3
ZZ6-ZZ9 = Assembly Note: SymbolCreator: codlsc

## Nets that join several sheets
12V_IN_B4JUMP: SV601263A_LED (D1.2), SV601263A_Power (J13.1 T1.2)
CAPHS_12: SV601263A_DS90UB921 (U1.17), SV601263A_Power (C39.1 C40.1 C41.1 C42.1)
CAPL12: SV601263A_DS90UB921 (U1.7), SV601263A_Power (C35.1 C36.1 C37.1 C38.1)
CAPP_12: SV601263A_DS90UB921 (U1.14), SV601263A_Power (C47.1 C48.1 C49.1 C50.1)
GND: SV601263A_CONFIG (25 pins), SV601263A_CONNECTORS (60 pins), SV601263A_DS90UB921 (34 pins), SV601263A_LED (17 pins), SV601263A_MSP430F5529 (31 pins), SV601263A_Power (79 pins)
VBUS: SV601263A_LED (D3.2), SV601263A_MSP430F5529 (5 pins)
VDD5V: SV601263A_LED (D4.2 D6.1), SV601263A_Power (6 pins)
VDD33: SV601263A_CONNECTORS (5 pins), SV601263A_DS90UB921 (J4.1), SV601263A_LED (D5.2), SV601263A_Power (5 pins)
VDD33_C: SV601263A_CONFIG (16 pins), SV601263A_DS90UB921 (U1.22), SV601263A_Power (C54.1 C55.1 C56.1 L7.2)
VDD_EXT: SV601263A_LED (D2.2), SV601263A_Power (12 pins)
VDDIO: SV601263A_DS90UB921 (J4.3), SV601263A_Power (5 pins)
VDDIO_C: SV601263A_DS90UB921 (R48.2 U1.30), SV601263A_Power (C62.1 C63.1 C64.1 L9.2)
CMF: SV601263A_DS90UB921 (U1.23), SV601263A_Power (C6.1 C7.1)
DE: SV601263A_CONNECTORS (J26.54), SV601263A_DS90UB921 (R68.1 U1.5)
DIN0/R0: SV601263A_CONNECTORS (J26.2 R121.2), SV601263A_DS90UB921 (R35.2 U1.25)
DIN1/R1: SV601263A_CONNECTORS (J26.4 R122.2), SV601263A_DS90UB921 (R36.1 U1.26)
DIN2/R2: SV601263A_CONNECTORS (J26.6), SV601263A_DS90UB921 (R38.1 U1.27)
DIN3/R3: SV601263A_CONNECTORS (J26.8), SV601263A_DS90UB921 (R40.1 U1.28)
DIN4/R4: SV601263A_CONNECTORS (J26.10), SV601263A_DS90UB921 (R41.1 U1.29)
DIN5/R5: SV601263A_CONNECTORS (J26.12), SV601263A_DS90UB921 (R42.1 U1.32)
DIN6/R6: SV601263A_CONNECTORS (J26.14), SV601263A_DS90UB921 (R43.1 U1.33)
DIN7/R7: SV601263A_CONNECTORS (J26.16), SV601263A_DS90UB921 (R44.1 U1.34)
DIN8/G0: SV601263A_CONNECTORS (J26.18 R123.2), SV601263A_DS90UB921 (R45.1 U1.35)
DIN9/G1: SV601263A_CONNECTORS (J26.20 R124.2), SV601263A_DS90UB921 (R46.1 U1.36)
DIN10/G2: SV601263A_CONNECTORS (J26.22), SV601263A_DS90UB921 (R47.1 U1.37)
DIN11/G3: SV601263A_CONNECTORS (J26.24), SV601263A_DS90UB921 (R49.1 U1.38)
DIN12/G4: SV601263A_CONNECTORS (J26.26), SV601263A_DS90UB921 (R50.1 U1.39)
DIN13/G5: SV601263A_CONNECTORS (J26.28), SV601263A_DS90UB921 (R51.1 U1.40)
DIN14/G6: SV601263A_CONNECTORS (J26.30), SV601263A_DS90UB921 (R52.1 U1.41)
DIN15/G7: SV601263A_CONNECTORS (J26.32), SV601263A_DS90UB921 (R54.1 U1.42)
DIN16/B0: SV601263A_CONNECTORS (J26.34 R125.2), SV601263A_DS90UB921 (R55.1 U1.43)
DIN17/B1: SV601263A_CONNECTORS (J26.36 R126.2), SV601263A_DS90UB921 (R57.1 U1.44)
DIN18/B2: SV601263A_CONNECTORS (J26.38), SV601263A_DS90UB921 (R58.1 U1.45)
DIN19/B3: SV601263A_CONNECTORS (J26.40), SV601263A_DS90UB921 (R59.1 U1.46)
DIN20/B4: SV601263A_CONNECTORS (J26.42), SV601263A_DS90UB921 (R60.1 U1.47)
DIN21/B5: SV601263A_CONNECTORS (J26.44), SV601263A_DS90UB921 (R61.1 U1.48)
DIN22/B6: SV601263A_CONNECTORS (J26.46), SV601263A_DS90UB921 (R62.1 U1.1)
DIN23/B7: SV601263A_CONNECTORS (J26.48), SV601263A_DS90UB921 (R63.1 U1.2)
DOUT_N: SV601263A_CONNECTORS (C81.2 C84.2), SV601263A_DS90UB921 (U1.19)
DOUT_P: SV601263A_CONNECTORS (C80.2 C82.2), SV601263A_DS90UB921 (U1.20)
FSEL: SV601263A_CONFIG (R32.1 S4.3), SV601263A_DS90UB921 (U1.15)
HS: SV601263A_CONNECTORS (J26.50), SV601263A_DS90UB921 (R66.1 U1.3)
I2S_CLK: SV601263A_CONNECTORS (J31.18), SV601263A_DS90UB921 (U1.13)
I2S_DA: SV601263A_CONNECTORS (J31.14), SV601263A_DS90UB921 (U1.11)
I2S_WC: SV601263A_CONNECTORS (J31.16), SV601263A_DS90UB921 (U1.12)
IDx: SV601263A_CONFIG (10 pins), SV601263A_DS90UB921 (U1.6)
MODE_SEL: SV601263A_CONFIG (10 pins), SV601263A_DS90UB921 (U1.24)
NetC3_1: SV601263A_CONFIG (5 pins), SV601263A_DS90UB921 (R64.2)
NetJ32_1: SV601263A_CONNECTORS (J32.1), SV601263A_DS90UB921 (R53.2), SV601263A_LED (Q1.1 R78.2)
PCLK: SV601263A_CONNECTORS (J26.56), SV601263A_DS90UB921 (R34.2 R65.1 U1.10)
REM_INTB: SV601263A_CONNECTORS (J31.20), SV601263A_DS90UB921 (U1.16)
SCL: SV601263A_CONNECTORS (R116.1 R118.1 U9.3), SV601263A_DS90UB921 (R39.2), SV601263A_MSP430F5529 (J10.2 R88.1)
SDA: SV601263A_CONNECTORS (R115.1 R119.1 U9.5), SV601263A_DS90UB921 (R37.2), SV601263A_MSP430F5529 (J10.1 R89.2)
VS: SV601263A_CONNECTORS (J26.52), SV601263A_DS90UB921 (R67.1 U1.4)

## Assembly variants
001: not fitted C6 C30 C31 C32 C33 C34 C35 C36 C40 C41 C42 C47 C48 C49 C53 C54 C55 C80 C81 J27 P1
